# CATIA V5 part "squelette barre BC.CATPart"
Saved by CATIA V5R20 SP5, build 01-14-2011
Part number: squelette barre BC
Publications: "Point.3", "Point.1", "Droite.2"
Bounding box of the stored display mesh (mm): x -20 to 0, y 0 to 200, z 200 to 200
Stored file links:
  F:\projet\yyang_IAO\squelette barre BC.CATPart
  F:\projet\yyang_IAO\iao.CATProduct
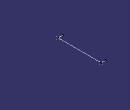
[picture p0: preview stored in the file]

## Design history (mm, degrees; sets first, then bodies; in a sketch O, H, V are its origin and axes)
External parameters (linked from other documents)
  `External.Longueur de barre AB et BC` = 200 mm
Set1
  Point1: linked copy from another document
  Plane1: linked copy from another document
Body1 (main body)
  Point2: (0, 0, 0), relative to Point1
  Line1: type PtDir, RefPoint Point1, Direction (1, 0, 0), Start 0, End 20
  Line2: type PtDir, RefPoint Point1, Direction (0, 1, 0), Start 0, End 200 {= `External.Longueur de barre AB et BC`}
  Point3: (0, 0, 0), relative to vertex of Line2
  Plane2: type Offset, RefPlane Plane1, Offset 0
  Line3: type PtDir, RefPoint Point3, Direction (1, 0, 0), Start 0, End 20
